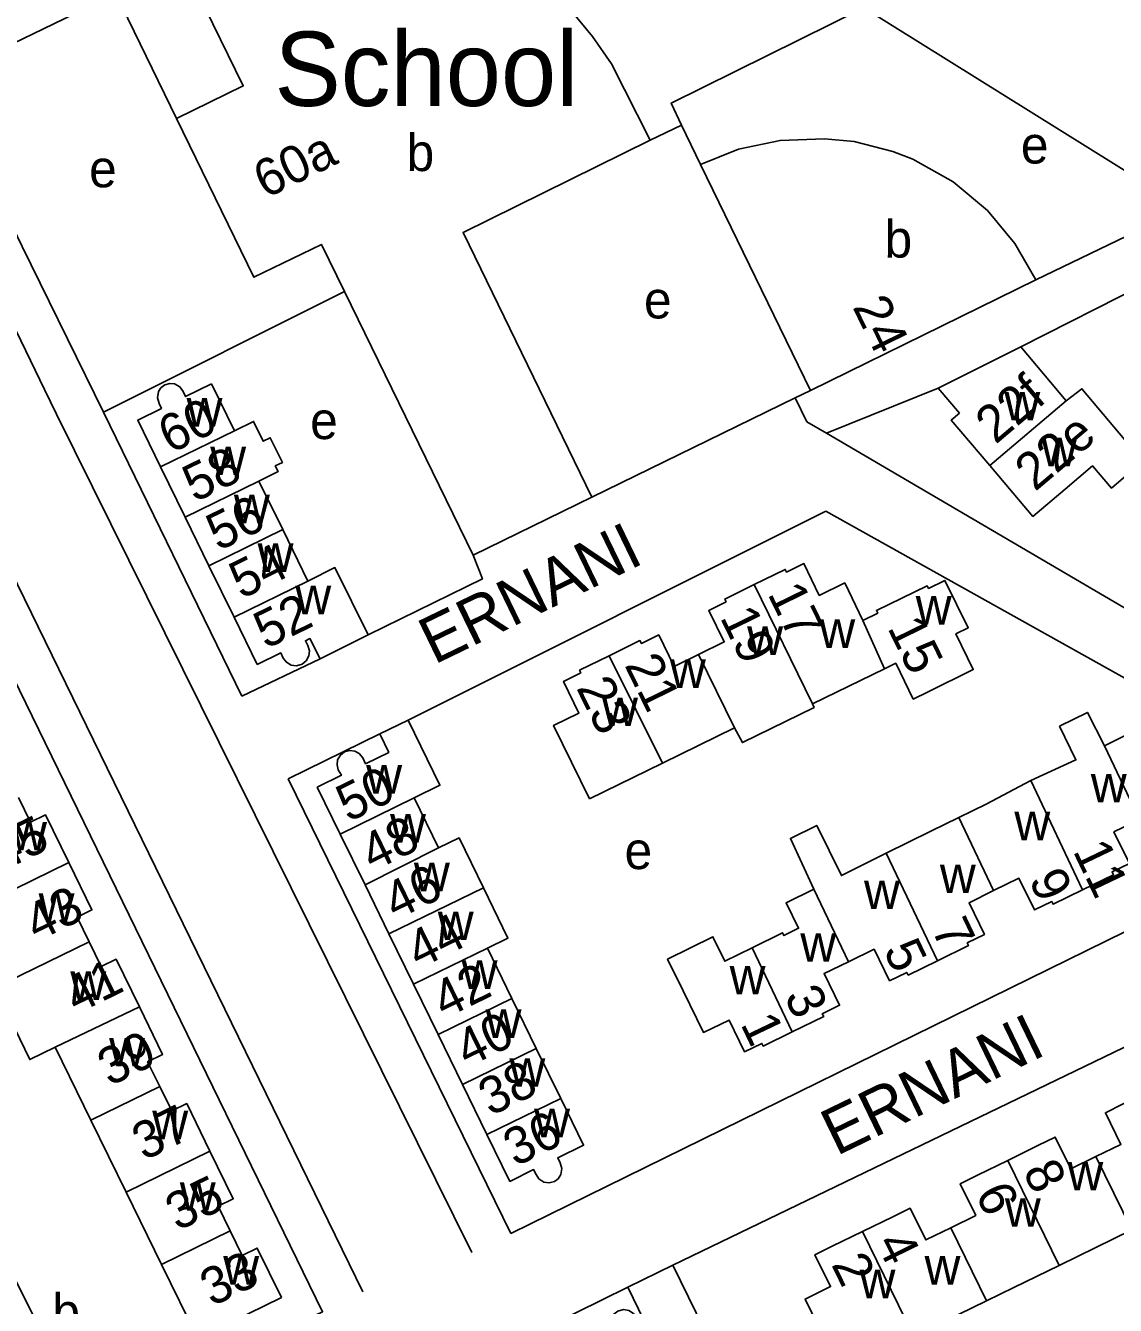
# Model space of a CAD drawing. Extents: x 159441 to 162086, y 388175 to 389787.
# Drawn here: x 161366.5 to 161483.8, y 389151.7 to 389289.4 of the extents above; entities that cross this region are included whole.
import ezdxf

# ---------------------------------------------------------------- set-up
doc = ezdxf.new("R2010")
doc.units = 0
for name, color, linetype in [('BLT_Basislijn', 7, 'Continuous'), ('BLT_Bebouwing', 7, 'Continuous'), ('BLT_Bebouwing_beschrifting', 7, 'Continuous'), ('BLT_Centroide', 7, 'Continuous'), ('BLT_Huisnummer', 7, 'Continuous'), ('BLT_Huisnummer_ tussenligend', 7, 'Continuous'), ('BLT_Onderverdeling_panden', 7, 'Continuous'), ('BLT_Straatnaam', 7, 'Continuous')]:
    doc.layers.add(name, color=color, linetype=linetype)

msp = doc.modelspace()

# ---------------------------------------------------------------- linework, layer by layer
at = {"layer": 'BLT_Basislijn'}
for p, q in [((161456.75, 389291.27), (161491.3, 389269.76)), ((161433.77, 389277.04), (161437.12, 389278.67)), ((161437.12, 389278.67), (161439.18, 389274.41)), ((161473.67, 389254.79), (161511.27, 389273.88)), ((161475.29, 389262), (161491.3, 389269.76)), ((161374.89, 389247.78), (161400.86, 389260.74)), ((161449.38, 389249.31), (161451.03, 389250.12)), ((161452.73, 389245.51), (161464.76, 389250.36)), ((161369.85, 389247.56), (161414.55, 389157.34)), ((161452.68, 389237.13), (161407.69, 389214.64)), ((161493.99, 389214.02), (161452.68, 389237.13)), ((161402.83, 389153.13), (161362.78, 389235.04)), ((161404.64, 389213.15), (161394.79, 389208.33)), ((161394.79, 389208.33), (161418.74, 389159.4)), ((161418.74, 389159.4), (161502.42, 389200.48))]:
    msp.add_line(p, q, dxfattribs=at)
for points in [[(161345.46, 389295.54), (161345.74, 389295.3), (161347.05, 389293.86), (161348.06, 389292.39), (161349.03, 389290.66), (161350.35, 389287.69), (161352.98, 389282.25), (161359.9, 389268.04), (161368.55, 389250.2), (161369.85, 389247.56)], [(161382.75, 389279.37), (161376.24, 389292.82), (161357.36, 389283.67)], [(161456.75, 389291.27), (161436.02, 389281.03), (161437.12, 389278.67)], [(161357.36, 389283.67), (161366.14, 389265.61), (161374.89, 389247.78)], [(161377.7, 389141.03), (161398.49, 389150.98), (161358.19, 389233.53), (161324.94, 389222.58), (161320, 389221.7), (161315.37, 389221.36), (161310.96, 389221.46), (161306.93, 389221.92), (161302.1, 389222.95), (161298.33, 389224.14), (161293.71, 389226.11), (161290.34, 389227.93), (161285.72, 389231.07), (161282.57, 389233.73), (161278.51, 389237.91), (161275.64, 389241.75), (161271.11, 389250.82), (161262.06, 389246.64)], [(161427.46, 389238.62), (161449.38, 389249.31)], [(161449.38, 389249.31), (161450.63, 389246.74), (161452.73, 389245.51)], [(161374.89, 389247.78), (161389.78, 389217.2)], [(161452.73, 389245.51), (161523.64, 389203.97)], [(161403.41, 389223.82), (161415.69, 389229.83), (161414.69, 389232.37)], [(161389.78, 389217.2), (161398.22, 389221.24)], [(161529.08, 389200.78), (161436.21, 389155.98)], [(161367.86, 389149.54), (161351.54, 389181.89), (161311.63, 389195.19)], [(161431.36, 389153.61), (161423.06, 389149.55), (161446.94, 389100.8), (161584.9, 389167.69)]]:
    msp.add_lwpolyline(points, dxfattribs=at)
at = {"layer": 'BLT_Bebouwing'}
for p, q in [((161473.67, 389254.79), (161464.76, 389250.36)), ((161478.56, 389248.99), (161473.67, 389254.79)), ((161464.76, 389250.36), (161467.05, 389247.66)), ((161404.64, 389213.15), (161407.69, 389214.64)), ((161442.82, 389213.8), (161435.08, 389210.01)), ((161435.08, 389210.01), (161427.21, 389206.16)), ((161397.92, 389207.43), (161400.38, 389202.38)), ((161410.96, 389200.88), (161408.33, 389206.27)), ((161400.38, 389202.38), (161403.06, 389196.9)), ((161403.06, 389196.9), (161405.63, 389191.64)), ((161405.63, 389191.64), (161408.28, 389186.21)), ((161418.86, 389184.7), (161416.23, 389190.1)), ((161408.28, 389186.21), (161410.92, 389180.82)), ((161421.5, 389179.31), (161418.86, 389184.7)), ((161410.92, 389180.82), (161413.55, 389175.43)), ((161369.7, 389179.46), (161373.54, 389171.61)), ((161424.13, 389173.93), (161421.5, 389179.31)), ((161413.55, 389175.43), (161416.18, 389170.05)), ((161373.54, 389171.61), (161377.34, 389163.85)), ((161377.34, 389163.85), (161381.14, 389156.07)), ((161477.79, 389155.97), (161485.61, 389159.78))]:
    msp.add_line(p, q, dxfattribs=at)
for points in [[(161382.22, 389298.65), (161385.9, 389300.24), (161392.81, 389302.09), (161396.59, 389302.49), (161399.97, 389302.49), (161403.62, 389302.18), (161406.98, 389301.53), (161410.36, 389300.54), (161413.77, 389299.23), (161417.01, 389297.53), (161419.89, 389295.62), (161422.9, 389293.21), (161425.31, 389290.9), (161427.55, 389288.2), (161429.58, 389285.25), (161433.77, 389277.04)], [(161383.39, 389296.28), (161389.95, 389282.88), (161382.75, 389279.37)], [(161382.75, 389279.37), (161391.09, 389262.29), (161398.37, 389265.83), (161400.86, 389260.74)], [(161427.46, 389238.62), (161413.61, 389267.11), (161433.77, 389277.04)], [(161439.18, 389274.41), (161443.26, 389276.07), (161447.75, 389277.02), (161452.53, 389277.18), (161455.72, 389276.88), (161459.89, 389275.82), (161462.05, 389274.98), (161466.39, 389272.54), (161470.06, 389269.47), (161473.03, 389265.92), (161475.29, 389262)], [(161439.18, 389274.41), (161451.03, 389250.12)], [(161451.03, 389250.12), (161475.29, 389262)], [(161400.86, 389260.74), (161414.69, 389232.37)], [(161381.04, 389241.88), (161378.58, 389246.92), (161381.14, 389248.18), (161380.88, 389248.72), (161380.7, 389249.31), (161380.82, 389250), (161381.08, 389250.39), (161381.5, 389250.72), (161382.03, 389250.86), (161382.55, 389250.81), (161383.11, 389250.5), (161383.47, 389250), (161383.74, 389249.45), (161386.52, 389250.81)], [(161386.52, 389250.81), (161388.99, 389245.76)], [(161470.33, 389242.02), (161474.96, 389236.56), (161478.43, 389239.49), (161481.39, 389241.99), (161483.41, 389239.6), (161487.5, 389243.06), (161485.48, 389245.45), (161484.81, 389244.82), (161480.24, 389250.3), (161478.56, 389248.99)], [(161467.05, 389247.66), (161466.17, 389246.93), (161470.33, 389242.02)], [(161388.99, 389245.76), (161391.06, 389246.77), (161392.1, 389244.65), (161392.86, 389245.03), (161394.16, 389242.37), (161393.39, 389241.99), (161393.69, 389241.38), (161391.64, 389240.35)], [(161383.7, 389236.46), (161381.04, 389241.88)], [(161391.64, 389240.35), (161394.19, 389235.14)], [(161414.69, 389232.37), (161427.46, 389238.62)], [(161386.24, 389231.25), (161383.7, 389236.46)], [(161394.19, 389235.14), (161396.9, 389229.6)], [(161388.95, 389225.71), (161386.24, 389231.25)], [(161403.41, 389223.82), (161399.82, 389231.05), (161396.9, 389229.6)], [(161444.96, 389229.22), (161448.3, 389230.86), (161448.44, 389230.56), (161450.31, 389231.48), (161451.97, 389228.06), (161454.71, 389229.4), (161456.67, 389225.37)], [(161456.67, 389225.37), (161458.26, 389226.15), (161458.11, 389226.44), (161463.58, 389229.1), (161463.73, 389228.81), (161465.5, 389229.67), (161468, 389224.57), (161466.67, 389223.92), (161468.55, 389220.07), (161463.61, 389217.65)], [(161438.96, 389221.7), (161441.73, 389223.06), (161440.06, 389226.45), (161441.93, 389227.37), (161441.79, 389227.67), (161444.96, 389229.22)], [(161391.43, 389220.63), (161388.95, 389225.71)], [(161391.43, 389220.63), (161393.98, 389221.89), (161394.26, 389221.29), (161394.59, 389220.87), (161395.11, 389220.56), (161395.69, 389220.48), (161396.28, 389220.65), (161396.73, 389221.02), (161397.01, 389221.56), (161397.07, 389222.09), (161396.89, 389222.68), (161396.64, 389223.18), (161397.13, 389223.42), (161398.22, 389221.24)], [(161398.22, 389221.24), (161403.41, 389223.82)], [(161429.34, 389221.57), (161432.66, 389223.19), (161432.81, 389222.9), (161434.68, 389223.81), (161436.34, 389220.42), (161438.96, 389221.7)], [(161427.21, 389206.16), (161423.35, 389214.07), (161426.09, 389215.4), (161424.43, 389218.8), (161426.29, 389219.71), (161426.15, 389220.01), (161429.34, 389221.57)], [(161458.98, 389220.16), (161451.24, 389216.38)], [(161463.61, 389217.65), (161462.09, 389216.91), (161460.2, 389220.76), (161458.98, 389220.16)], [(161451.24, 389216.38), (161451.41, 389216.01), (161443.69, 389212.23), (161442.82, 389213.8)], [(161408.33, 389206.27), (161411.12, 389207.63), (161407.69, 389214.64)], [(161482.67, 389211.87), (161480.84, 389215.46), (161477.82, 389213.97)], [(161404.64, 389213.15), (161405.61, 389211.17), (161403.12, 389209.95), (161402.81, 389210.59), (161402.44, 389211.04), (161401.97, 389211.3), (161401.41, 389211.37), (161400.85, 389211.22), (161400.41, 389210.88), (161400.11, 389210.35), (161400.04, 389209.84), (161400.18, 389209.28), (161400.52, 389208.71), (161397.92, 389207.43)], [(161477.82, 389213.97), (161479.6, 389210.36), (161474.74, 389208.13)], [(161493.99, 389214.02), (161486.91, 389210.54), (161485.55, 389213.29), (161482.67, 389211.87)], [(161474.74, 389208.13), (161469.94, 389205.61), (161466.99, 389204.15)], [(161371.16, 389199.33), (161368.65, 389204.45), (161367.04, 389203.66), (161365.74, 389206.31)], [(161459.18, 389200.31), (161454.34, 389197.91), (161451.69, 389203.3), (161448.86, 389201.91), (161451.38, 389196.45)], [(161466.99, 389204.15), (161463.99, 389202.68), (161459.18, 389200.31)], [(161480.32, 389196.39), (161483.63, 389198), (161483.49, 389198.3), (161485.35, 389199.21), (161483.68, 389202.61), (161486.44, 389203.96)], [(161415.82, 389196.58), (161413.19, 389201.97), (161410.96, 389200.88)], [(161373.34, 389190.77), (161372.05, 389193.42), (161372.86, 389193.82), (161373.66, 389194.21), (161371.16, 389199.33)], [(161416.23, 389190.1), (161418.45, 389191.19), (161415.82, 389196.58)], [(161451.38, 389196.45), (161448.39, 389194.98), (161449.74, 389192.24), (161448.16, 389191.46), (161448.02, 389191.76), (161444.75, 389190.15)], [(161470.74, 389196.29), (161473.46, 389197.62), (161475.13, 389194.21), (161476.99, 389195.12), (161477.13, 389194.83), (161480.32, 389196.39)], [(161464.7, 389188.75), (161468.03, 389190.38), (161467.89, 389190.67), (161469.75, 389191.58), (161468.09, 389194.99), (161470.74, 389196.29)], [(161444.75, 389190.15), (161441.81, 389188.7), (161440.52, 389191.33), (161435.64, 389188.92), (161437.3, 389185.52)], [(161378.76, 389183.79), (161376.26, 389188.91), (161374.64, 389188.12), (161373.34, 389190.77)], [(161455.1, 389188.64), (161457.87, 389189.99), (161459.53, 389186.59), (161461.39, 389187.5), (161461.54, 389187.2), (161464.7, 389188.75)], [(161449.06, 389181.1), (161452.44, 389182.75), (161452.29, 389183.05), (161454.15, 389183.96), (161452.49, 389187.36), (161455.1, 389188.64)], [(161365.94, 389187.15), (161363.19, 389185.82), (161366.96, 389178.12), (161369.7, 389179.46)], [(161437.3, 389185.52), (161439.49, 389181.03), (161442.25, 389182.36), (161443.9, 389178.95), (161445.78, 389179.86), (161445.93, 389179.56), (161449.06, 389181.1)], [(161380.95, 389175.23), (161379.65, 389177.88), (161381.26, 389178.67), (161378.76, 389183.79)], [(161386.36, 389168.25), (161383.86, 389173.37), (161382.24, 389172.58), (161380.95, 389175.23)], [(161481.74, 389167.68), (161484.44, 389168.99), (161482.77, 389172.4), (161484.63, 389173.32), (161487.89, 389174.91)], [(161416.18, 389170.05), (161418.65, 389165.01), (161421.21, 389166.27), (161421.48, 389165.73), (161421.78, 389165.27), (161422.3, 389164.94), (161422.87, 389164.85), (161423.44, 389164.99), (161423.85, 389165.29), (161424.15, 389165.75), (161424.25, 389166.41), (161424.07, 389166.99), (161423.81, 389167.53), (161426.59, 389168.89), (161424.13, 389173.93)], [(161472.26, 389167.26), (161475.51, 389168.85), (161477.38, 389169.77), (161479.05, 389166.36), (161481.74, 389167.68)], [(161388.55, 389159.69), (161387.25, 389162.34), (161388.87, 389163.13), (161386.36, 389168.25)], [(161466.12, 389160.02), (161468.81, 389161.34), (161467.14, 389164.75), (161469, 389165.67), (161472.26, 389167.26)], [(161456.63, 389159.61), (161459.88, 389161.2), (161461.75, 389162.11), (161463.42, 389158.7), (161466.12, 389160.02)], [(161381.14, 389156.07), (161385.04, 389148.11), (161394.05, 389152.52), (161391.46, 389157.83), (161389.84, 389157.04), (161388.55, 389159.69)], [(161452.62, 389147.85), (161450.43, 389152.34), (161453.18, 389153.69), (161451.5, 389157.11), (161453.37, 389158.02), (161456.63, 389159.61)], [(161436.21, 389155.98), (161431.36, 389153.61)], [(161440.39, 389147.43), (161436.21, 389155.98)], [(161472.93, 389153.59), (161477.79, 389155.97)], [(161431.36, 389153.61), (161433.09, 389150.07), (161432.55, 389149.81), (161432.27, 389150.34), (161431.95, 389150.79), (161431.45, 389151.11), (161430.87, 389151.21), (161430.28, 389151.06), (161429.83, 389150.72), (161429.53, 389150.19), (161429.46, 389149.62), (161429.63, 389149.05), (161429.89, 389148.51), (161427.34, 389147.26)], [(161469.97, 389152.15), (161472.93, 389153.59)], [(161462.16, 389148.32), (161466.97, 389150.68), (161469.97, 389152.15)]]:
    msp.add_lwpolyline(points, dxfattribs=at)
at = {"layer": 'BLT_Onderverdeling_panden'}
for p, q in [((161470.33, 389242.02), (161478.56, 389248.99)), ((161381.04, 389241.88), (161388.99, 389245.76)), ((161383.7, 389236.46), (161391.64, 389240.35)), ((161386.24, 389231.25), (161394.19, 389235.14)), ((161388.95, 389225.71), (161396.9, 389229.6)), ((161444.96, 389229.22), (161451.24, 389216.38)), ((161456.67, 389225.37), (161458.98, 389220.16)), ((161435.08, 389210.01), (161429.34, 389221.57)), ((161438.96, 389221.7), (161442.82, 389213.8)), ((161486.44, 389203.96), (161482.67, 389211.87)), ((161474.74, 389208.13), (161480.32, 389196.39)), ((161400.38, 389202.38), (161408.33, 389206.27)), ((161466.99, 389204.15), (161470.74, 389196.29)), ((161403.06, 389196.9), (161410.96, 389200.88)), ((161371.16, 389199.33), (161362.14, 389194.92)), ((161459.18, 389200.31), (161464.7, 389188.75)), ((161405.63, 389191.64), (161415.82, 389196.58)), ((161451.38, 389196.45), (161455.1, 389188.64)), ((161373.34, 389190.77), (161365.94, 389187.15)), ((161408.28, 389186.21), (161416.23, 389190.1)), ((161444.75, 389190.15), (161449.06, 389181.1)), ((161410.92, 389180.82), (161418.86, 389184.7)), ((161378.76, 389183.79), (161369.7, 389179.46)), ((161413.55, 389175.43), (161421.5, 389179.31)), ((161380.95, 389175.23), (161373.54, 389171.61)), ((161416.18, 389170.05), (161424.13, 389173.93)), ((161386.36, 389168.25), (161377.34, 389163.85)), ((161481.74, 389167.68), (161485.61, 389159.78)), ((161472.26, 389167.26), (161477.79, 389155.97)), ((161388.55, 389159.69), (161381.14, 389156.07)), ((161456.63, 389159.61), (161462.16, 389148.32)), ((161466.12, 389160.02), (161469.97, 389152.15))]:
    msp.add_line(p, q, dxfattribs=at)

# ---------------------------------------------------------------- texts
at = {"layer": 'BLT_Bebouwing_beschrifting'}
msp.add_text('School', height=8, dxfattribs=at).set_placement((161393.31, 389280.72))
at = {"layer": 'BLT_Centroide'}
for s, p in [('b', (161407.53, 389273.72)), ('e', (161473.67, 389274.53)), ('e', (161373.35, 389271.97)), ('b', (161458.99, 389264.41)), ('e', (161433.09, 389257.86)), ('w', (161383.84, 389246.22)), ('w', (161471.89, 389246.88)), ('e', (161397.15, 389244.88)), ('w', (161475.87, 389241.96)), ('w', (161386.39, 389241)), ('w', (161388.94, 389235.81)), ('w', (161391.49, 389230.59)), ('w', (161395.55, 389226.03)), ('w', (161462.35, 389224.91)), ('w', (161451.97, 389222.41)), ('w', (161444.2, 389221.66)), ('w', (161435.88, 389218.09)), ('w', (161428.58, 389214)), ('w', (161403.18, 389206.72)), ('w', (161481.2, 389205.78)), ('w', (161472.97, 389201.72)), ('w', (161364.95, 389200.62)), ('w', (161405.75, 389201.47)), ('e', (161431, 389198.61)), ('w', (161408.32, 389196.22)), ('w', (161464.95, 389196.02)), ('w', (161456.78, 389194.3)), ('w', (161367.91, 389192.94)), ('w', (161410.89, 389190.97)), ('w', (161449.92, 389188.64)), ('w', (161413.46, 389185.72)), ('w', (161442.31, 389185.12)), ('w', (161371.33, 389184.53)), ('w', (161416.04, 389180.44)), ('w', (161375.5, 389177.38)), ('w', (161418.6, 389175.19)), ('w', (161380.15, 389169.53)), ('w', (161421.26, 389169.75)), ('w', (161478.68, 389164.03)), ('w', (161383.11, 389161.84)), ('w', (161471.95, 389160.12)), ('w', (161387.79, 389153.91)), ('w', (161463.3, 389153.91)), ('w', (161456.3, 389152.44)), ('b', (161369.4, 389148.94))]:
    msp.add_text(s, height=4, dxfattribs=at).set_placement(p)
at = {"layer": 'BLT_Huisnummer'}
for s, rotation, p in [('60a', 26.0679, (161392.34, 389270.71)), ('24', 296.087, (161455.5, 389259.11)), ('22f', 40.2031, (161470.94, 389244.24)), ('60', 26.0654, (161382.09, 389243.26)), ('22e', 40.2031, (161475.19, 389239.16)), ('56', 26.0654, (161387.26, 389232.78)), ('52', 26.0654, (161392.37, 389222.24)), ('19', 296.0611, (161441.23, 389225.71)), ('15', 296.064, (161459.25, 389224.6)), ('23', 296.0611, (161425.76, 389218.12)), ('50', 26.0654, (161401.25, 389203.61)), ('45', 26.0596, (161363.99, 389198.33)), ('9', 295.5173, (161474.47, 389197.47)), ('44', 26.0654, (161408.83, 389187.83)), ('5', 295.5173, (161458.82, 389189.88)), ('41', 26.0596, (161371.98, 389182.96)), ('40', 26.0654, (161414.07, 389177.22)), ('1', 295.5173, (161443.44, 389181.96)), ('37', 26.0596, (161379.27, 389167.19)), ('36', 26.0654, (161419.24, 389166.54)), ('6', 296.0706, (161468.71, 389163.66)), ('33', 26.0596, (161386.59, 389151.49)), ('2', 296.0706, (161453.22, 389156.08))]:
    msp.add_text(s, height=4, rotation=rotation, dxfattribs=at).set_placement(p)
at = {"layer": 'BLT_Huisnummer_ tussenligend'}
for s, rotation, p in [('58', 26.0654, (161384.71, 389238.02)), ('54', 26.0654, (161389.74, 389227.61)), ('17', 296.0611, (161446.35, 389228.25)), ('21', 296.0611, (161430.95, 389220.58)), ('48', 26.0654, (161403.87, 389198.31)), ('11', 295.5173, (161479.23, 389200.57)), ('46', 26.0654, (161406.35, 389193.07)), ('43', 26.0596, (161367.71, 389190.76)), ('7', 295.5173, (161463.99, 389192.17)), ('42', 26.0654, (161411.6, 389182.46)), ('3', 295.5173, (161448.14, 389184.92)), ('39', 26.0596, (161375.56, 389175.19)), ('38', 26.0654, (161416.56, 389171.98)), ('8', 296.0706, (161473.83, 389166.1)), ('35', 26.0596, (161382.87, 389159.62)), ('4', 296.0706, (161458.03, 389158.39))]:
    msp.add_text(s, height=4, rotation=rotation, dxfattribs=at).set_placement(p)
at = {"layer": 'BLT_Straatnaam'}
for p in [(161410.5, 389220.57), (161453.81, 389167.7)]:
    msp.add_text('ERNANI', height=5, rotation=25.8394, dxfattribs=at).set_placement(p)

doc.saveas('drawing.dxf')
